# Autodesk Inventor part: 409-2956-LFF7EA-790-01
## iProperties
Shininess: 64.0
Angle Display Precision: 2
Document Length Units: 11272
Document Angle Units: 11279
Document Time Units: 11290
Document Mass Units: 11286
Document Length Units Precision: 3
Document Angle Units Precision: 2
Compacted: True
Created: 2002-04
Part Number: 409-2956-LFF7EA-790-01
Description: 3" PIPE MOUNT ANGLE
Document SubType Name: Modeling
Designer: S. Boerckel
Mass: 826.332 g
Surface Area: 360.435 cm^2
Volume: 105.265 cm^3
Density: 7.85 g/cm^3
Cost Center: 2 x 2 x 1/4 ANGLE
Material: ASTM A36
Engineer: S. Boerckel
User Status: SAW/PUNCH
Density: 0.0
Volumn: 0.0
Area: 0.0
PropertySet Name: Model Information
Control State: 0
Master: False
Checked Out: False
length: 7.000 in
SMR: =<COST CENTER> - <MATERIAL>
Author: S. Boerckel
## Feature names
1. Extrusion1
2. Hole1
